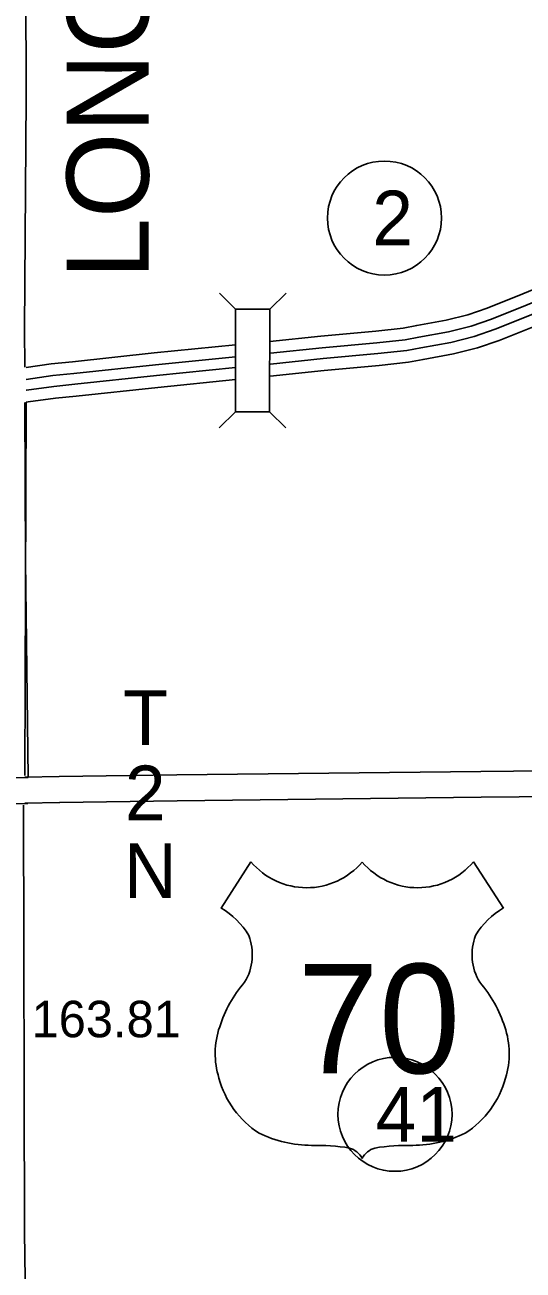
# Model space of a CAD drawing. Extents: x 1127717 to 1741049, y 2026793 to 2244711.
# Drawn here: x 1247728 to 1250609, y 2133375 to 2140586 of the extents above; entities that cross this region are included whole.
import ezdxf

# ---------------------------------------------------------------- set-up
doc = ezdxf.new("R2010")
doc.units = 0
for name, color, linetype in [('15', 7, 'Continuous'), ('19', 7, 'Continuous'), ('2', 7, 'Continuous'), ('20', 7, 'Continuous'), ('22', 7, 'Continuous'), ('25', 7, 'Continuous'), ('27', 7, 'Continuous'), ('30', 7, 'Continuous'), ('Level 30', 7, 'Continuous')]:
    doc.layers.add(name, color=color, linetype=linetype)

msp = doc.modelspace()

# ---------------------------------------------------------------- linework, layer by layer
at = {"layer": '15'}
for points in [[(1247926.1, 2136233), (1248605.8, 2136242.9), (1250364.1, 2136263.1), (1251684.6, 2136274.9), (1253253.5, 2136287.2), (1253554.6, 2136290)], [(1246661.3, 2136204.1), (1247745.5, 2136227)], [(1247727.7, 2136228.8), (1247925.6, 2136232.9)], [(1247928.3, 2136083), (1248607.7, 2136092.9), (1250365.7, 2136113.1), (1251685.8, 2136124.9), (1253254.8, 2136137.2), (1253556, 2136140)], [(1246663.5, 2136054.1), (1247745, 2136077)], [(1247727.7, 2136078.7), (1247928.8, 2136083)]]:
    msp.add_lwpolyline(points, dxfattribs=at)
at = {"layer": '19'}
for points in [[(1249143.7, 2138753.3), (1249439.8, 2138783.8), (1249756.6, 2138813.2), (1249916.1, 2138829.9), (1249993.8, 2138845.4), (1250163.8, 2138875.7), (1250288.4, 2138907.4), (1250401.9, 2138946.2), (1250607.3, 2139027.9), (1250739.3, 2139081.8), (1250959, 2139171.4), (1251152.2, 2139252.3), (1251348.1, 2139339.6), (1251540.1, 2139418.3), (1251694, 2139479.8), (1251822.1, 2139538.9), (1251979.2, 2139596.7), (1252136.3, 2139641.8), (1252301.1, 2139672.4), (1252472.4, 2139704.4), (1252617.5, 2139720), (1252789.9, 2139733), (1253043.4, 2139746.9), (1253450.6, 2139777.9)], [(1249147.6, 2138684.6), (1249446.5, 2138715.4), (1249763.3, 2138744.8), (1249926.4, 2138761.9), (1250006.6, 2138777.8), (1250178.3, 2138808.5), (1250308.1, 2138841.4), (1250425.7, 2138881.7), (1250633, 2138964.1), (1250765.3, 2139018.1), (1250985.2, 2139107.8), (1251179.4, 2139189.2), (1251375.2, 2139276.3), (1251565.9, 2139354.6), (1251721.1, 2139416.6), (1251848.4, 2139475.3), (1252000.6, 2139531.4), (1252152.1, 2139574.8), (1252313.7, 2139604.8), (1252482.4, 2139636.3), (1252623.8, 2139651.5), (1252794.3, 2139664.4), (1253047.9, 2139678.3), (1253455.8, 2139709.4)], [(1249147.9, 2138621.8), (1249452.6, 2138653.2), (1249769.5, 2138682.6), (1249935.8, 2138700), (1250018.1, 2138716.4), (1250191.5, 2138747.4), (1250325.9, 2138781.5), (1250447.4, 2138823.1), (1250656.4, 2138906.1), (1250788.9, 2138960.2), (1251009.1, 2139050.1), (1251204.2, 2139131.8), (1251399.7, 2139218.9), (1251589.4, 2139296.7), (1251745.8, 2139359.2), (1251872.3, 2139417.5), (1252020, 2139471.9), (1252166.5, 2139513.9), (1252325.1, 2139543.3), (1252491.5, 2139574.4), (1252629.5, 2139589.3), (1252798.4, 2139602), (1253052, 2139615.9), (1253460.6, 2139647.1)], [(1249146, 2138552.5), (1249459.3, 2138584.8), (1249776.2, 2138614.2), (1249946.1, 2138632), (1250030.9, 2138648.8), (1250206, 2138680.1), (1250345.6, 2138715.5), (1250471.2, 2138758.6), (1250682, 2138842.3), (1250814.9, 2138896.6), (1251035.4, 2138986.5), (1251231.5, 2139068.7), (1251426.8, 2139155.7), (1251615.2, 2139232.9), (1251773, 2139296), (1251898.7, 2139354), (1252041.4, 2139406.5), (1252182.2, 2139446.9), (1252337.7, 2139475.7), (1252501.5, 2139506.3), (1252635.8, 2139520.8), (1252802.8, 2139533.4), (1253056.5, 2139547.3), (1253465.8, 2139578.5)], [(1248002.7, 2138635.4), (1248475.1, 2138685.9), (1248946.2, 2138733)], [(1248010, 2138567.1), (1248482.2, 2138617.5), (1248946, 2138663.9)], [(1247734.3, 2138602.8), (1247880.1, 2138623.1), (1248003.3, 2138635.5)], [(1248016.7, 2138504.9), (1248488.6, 2138555.4), (1248945.9, 2138601.1)], [(1247734.4, 2138533.3), (1247888.2, 2138554.8), (1248010.2, 2138567.1)], [(1248024, 2138436.6), (1248495.7, 2138487), (1248946.3, 2138532)], [(1247734.4, 2138400.6), (1247746.1, 2138402.5), (1247903.9, 2138424.5), (1248023.3, 2138436.5)], [(1247735.2, 2138470.3), (1247736.1, 2138470.5), (1247895.7, 2138492.8), (1248016.5, 2138504.9)]]:
    msp.add_lwpolyline(points, dxfattribs=at)
at = {"layer": '2'}
for points in [[(1247663.1, 2144020.7), (1247662.8, 2142760.5), (1247726.6, 2142761.9), (1247731.3, 2141494.2), (1247734.4, 2140166.2), (1247725.8, 2138824.4), (1247726.7, 2138603.6)], [(1247727.6, 2138398.7), (1247731.3, 2137481), (1247745.5, 2136227)], [(1247734, 2138400.8), (1247727.7, 2136239.8)], [(1247719.9, 2136068.2), (1247726, 2133591.9), (1247745.1, 2132243.6)]]:
    msp.add_lwpolyline(points, dxfattribs=at)
at = {"layer": '20'}
for p, q in [((1248946.2, 2138939.8), (1248853, 2139033.3)), ((1249144.2, 2138939.3), (1249237.7, 2139032.5)), ((1248944.9, 2138345.8), (1248851.4, 2138252.6)), ((1249142.9, 2138345.3), (1249236.1, 2138251.8))]:
    msp.add_line(p, q, dxfattribs=at)
msp.add_lwpolyline([(1248946.2, 2138939.8), (1248944.9, 2138345.8), (1249142.9, 2138345.3), (1249144.2, 2138939.3)], close=True, dxfattribs=at)
at = {"layer": '22'}
for p, q in [((1249034.8, 2135739), (1248861.7, 2135471.4)), ((1250321.7, 2135739), (1250494.8, 2135471.4))]:
    msp.add_line(p, q, dxfattribs=at)
for centre, radius, start, end in [((1249357.1, 2136010.2), 421.2, 220.07504, 319.67012), ((1249999.4, 2136010.2), 421.2, 220.32988, 319.92496), ((1248635.6, 2135082.8), 449.7, 30.7809, 59.98827), ((1250720.9, 2135082.8), 449.7, 120.01173, 149.2191), ((1248734.5, 2135201.4), 308.3, 328.81046, 21.21077), ((1250622, 2135201.4), 308.3, 158.78923, 211.18954), ((1249540.6, 2134569.5), 719.2, 138.95648, 162.69135), ((1249815.9, 2134569.5), 719.2, 17.30865, 41.04352), ((1249303.2, 2134628.4), 475.2, 160.95764, 197.38186), ((1250053.3, 2134628.4), 475.2, 342.61814, 19.04236), ((1249380.6, 2134629.8), 549.9, 195.10743, 237.13119), ((1249975.9, 2134629.8), 549.9, 302.86881, 344.89257), ((1249390.8, 2134803), 706, 244.07708, 269.57785), ((1249965.7, 2134803), 706, 270.42215, 295.92292), ((1249407.1, 2132803.8), 1293.3, 81.19416, 90.95387), ((1249568.9, 2133963.4), 123.9, 28.03422, 72.98637), ((1249787.6, 2133963.4), 123.9, 107.01363, 151.96578), ((1249949.4, 2132803.8), 1293.3, 89.04613, 98.80584)]:
    msp.add_arc(centre, radius, start, end, dxfattribs=at)
at = {"layer": '27'}
for centre in [(1249807.3, 2139467.5), (1249867.8, 2134276.8)]:
    msp.add_circle(centre, 330, dxfattribs=at)

# ---------------------------------------------------------------- texts
at = {"layer": '22'}
msp.add_text('70', height=633.6, dxfattribs=at).set_placement((1249303.3, 2134514.8))
at = {"layer": '25'}
msp.add_text('163.81', height=211.2, dxfattribs=at).set_placement((1247765.8, 2134723.3))
at = {"layer": '27'}
for s, p in [('2', (1249736.5, 2139309.1)), ('41', (1249755.6, 2134118.4))]:
    msp.add_text(s, height=316.8, dxfattribs=at).set_placement(p)
at = {"layer": '30'}
for s, p in [('T', (1248295.8, 2136416)), ('2', (1248305.7, 2135979.6)), ('N', (1248299.8, 2135529.2))]:
    msp.add_text(s, height=316.8, dxfattribs=at).set_placement(p)
at = {"layer": 'Level 30'}
msp.add_text('LONOKE COUNTY', height=475.199, rotation=89.9667, dxfattribs=at).set_placement((1248443.3, 2139114.5))

doc.saveas('drawing.dxf')
